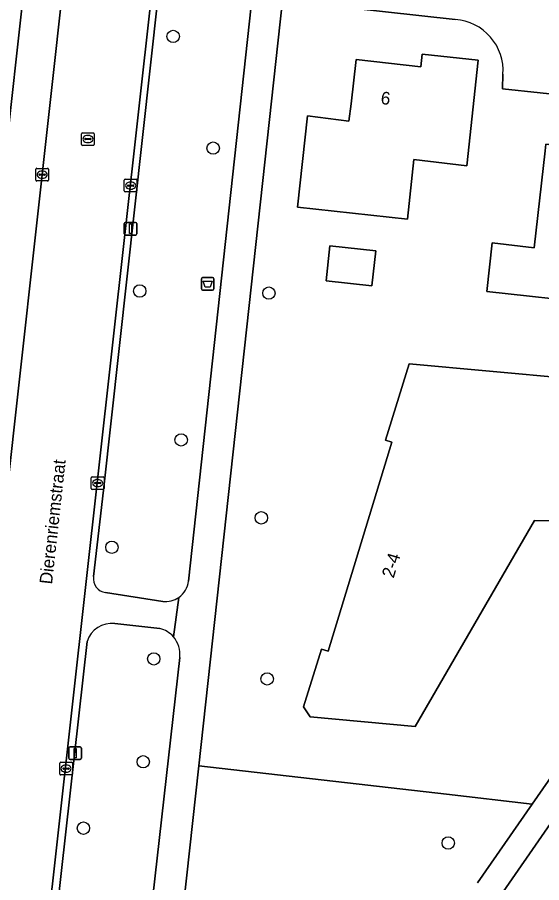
# Model space of a CAD drawing. Extents: x 161928 to 163071, y 386474 to 387428.
# Drawn here: x 162381 to 162422.4, y 386555.8 to 386624.1 of the extents above; entities that cross this region are included whole.
import ezdxf

# ---------------------------------------------------------------- set-up
doc = ezdxf.new("R2010")
doc.units = 0
for name, color, linetype in [('IMGEO_Afvalbak', 7, 'Continuous'), ('IMGEO_Boom', 7, 'Continuous'), ('IMGEO_Erf', 7, 'Continuous'), ('IMGEO_Groenvoorziening', 7, 'Continuous'), ('IMGEO_Kolk', 7, 'Continuous'), ('IMGEO_Lichtmast', 7, 'Continuous'), ('IMGEO_Openbare_ruimte_label', 7, 'Continuous'), ('IMGEO_Pand', 7, 'Continuous'), ('IMGEO_Pand_nummerreeks', 7, 'Continuous'), ('IMGEO_Rijbaan_lokaal_open', 7, 'Continuous'), ('IMGEO_Rioolput', 7, 'Continuous'), ('IMGEO_Voetpad_halfverhard', 7, 'Continuous'), ('IMGEO_Voetpad_open', 7, 'Continuous')]:
    doc.layers.add(name, color=color, linetype=linetype)

msp = doc.modelspace()

# ---------------------------------------------------------------- linework, layer by layer
at = {"layer": 'IMGEO_Afvalbak'}
for p, q in [((162395.637, 386603.544), (162396.427, 386603.544)), ((162396.427, 386603.544), (162395.637, 386603.544)), ((162395.537, 386602.644), (162395.537, 386603.444)), ((162395.537, 386603.444), (162395.537, 386602.644)), ((162396.527, 386603.444), (162396.527, 386602.644)), ((162396.527, 386602.644), (162396.527, 386603.444)), ((162396.427, 386602.544), (162395.637, 386602.544)), ((162395.637, 386602.544), (162396.427, 386602.544))]:
    msp.add_line(p, q, dxfattribs=at)
msp.add_lwpolyline([(162395.68, 386603.258), (162396.384, 386603.258), (162396.235, 386602.788), (162395.829, 386602.788), (162395.68, 386603.258)], dxfattribs=at)
for centre, start, end in [((162395.637, 386603.444), 90, 180), ((162395.637, 386603.444), 90, 180), ((162396.427, 386603.444), 0, 90), ((162396.427, 386603.444), 360, 90), ((162395.637, 386602.644), 180, 270), ((162395.637, 386602.644), 180, 270), ((162396.427, 386602.644), 270, 0), ((162396.427, 386602.644), 270, 0)]:
    msp.add_arc(centre, 0.1, start, end, dxfattribs=at)
at = {"layer": 'IMGEO_Boom'}
for centre in [(162393.313, 386622.577), (162396.47, 386613.757), (162390.674, 386602.473), (162400.87, 386602.31), (162393.945, 386590.715), (162400.269, 386584.564), (162388.477, 386582.239), (162391.784, 386573.428), (162400.731, 386571.846), (162390.949, 386565.307), (162386.227, 386560.062), (162415.023, 386558.889)]:
    msp.add_circle(centre, 0.489, dxfattribs=at)
at = {"layer": 'IMGEO_Erf'}
for points in [[(162339.209, 386621.347), (162355.58, 386619.565), (162355.871, 386622.182), (162359.601, 386621.768), (162363.559, 386621.328), (162363.268, 386618.711), (162367.629, 386618.152), (162367.92, 386620.769), (162371.65, 386620.355), (162375.608, 386619.915), (162375.317, 386617.298), (162380.485, 386616.728), (162382.904, 386638.649)], [(162415.579, 386623.904), (162401.954, 386625.399), (162400.548, 386612.657), (162395.336, 386564.99), (162414.895, 386562.738), (162421.638, 386561.962), (162444.564, 386594.917), (162445.356, 386594.4), (162447.893, 386598.102), (162459.435, 386614.943), (162461.829, 386626.715), (162463.03, 386628.501), (162454.731, 386634.129)], [(162420.711, 386632.302), (162420.785, 386633.326), (162432.793, 386632.1), (162431.191, 386617.163), (162419.313, 386618.428), (162419.342, 386619.587)]]:
    msp.add_lwpolyline(points, dxfattribs=at)
for points in [[(162416.478, 386612.365), (162412.312, 386612.86), (162411.796, 386608.156), (162403.125, 386609.105), (162403.907, 386616.296), (162407.183, 386615.892), (162407.356, 386617.249), (162407.76, 386620.758), (162412.848, 386620.178), (162412.963, 386621.184), (162417.396, 386620.697)], [(162427.798, 386613.519), (162427.904, 386614.49), (162432.344, 386614.004), (162432.984, 386613.934), (162433.301, 386616.837), (162438.553, 386614.056), (162438.131, 386610.243), (162433.019, 386610.774), (162431.843, 386609.181), (162432.687, 386609.076), (162432.443, 386606.776), (162431.59, 386606.862), (162431.44, 386605.691), (162427.261, 386606.138), (162426.729, 386601.484), (162418.06, 386602.436), (162418.497, 386606.268), (162421.797, 386605.894), (162422.663, 386613.546), (162422.722, 386614.071)], [(162408.995, 386602.89), (162405.381, 386603.285), (162405.682, 386606.038), (162409.296, 386605.643)], [(162425.465, 386590.661), (162426.325, 386592.104), (162427.514, 386591.415), (162423.4, 386584.325), (162421.823, 386584.367), (162412.423, 386568.098), (162404.117, 386568.856), (162403.593, 386569.649), (162405.008, 386574.185), (162405.538, 386574.032), (162410.561, 386590.527), (162410.059, 386590.685), (162411.937, 386596.728), (162424.617, 386595.56)]]:
    msp.add_lwpolyline(points, close=True, dxfattribs=at)
msp.add_arc((162415.314, 386619.874), 4.038, 355.91886, 86.23653, dxfattribs=at)
at = {"layer": 'IMGEO_Groenvoorziening'}
for points in [[(162399.459, 386624.985), (162398.864, 386625.051), (162392.123, 386625.803), (162387.805, 386586.742), (162387.016, 386579.921)], [(162394.525, 386579.576), (162399.459, 386624.985)], [(162440.702, 386585.864), (162418.182, 386553.338), (162417.153, 386552.158), (162415.924, 386550.971), (162414.594, 386549.899), (162413.174, 386548.95), (162411.674, 386548.131), (162410.108, 386547.45), (162408.487, 386546.912), (162406.824, 386546.52), (162405.699, 386546.306), (162403.155, 386545.99), (162400.592, 386545.903), (162398.032, 386546.045), (162393.322, 386546.486), (162403.05, 386533.82), (162404.756, 386535.016), (162406.178, 386535.73), (162416.358, 386539.36), (162419.33, 386541.041), (162421.413, 386542.569), (162422.397, 386543.77), (162427.166, 386551.666)], [(162387.976, 386578.658), (162392.493, 386577.97)], [(162392.272, 386575.826), (162388.696, 386576.225)], [(162386.515, 386574.809), (162383.807, 386550.605), (162391.149, 386549.775), (162393.833, 386573.529)], [(162421.638, 386561.962), (162414.895, 386562.738), (162395.336, 386564.99), (162393.659, 386549.647), (162400.359, 386548.883)], [(162417.322, 386555.758), (162421.638, 386561.962)]]:
    msp.add_lwpolyline(points, dxfattribs=at)
for centre, radius, start, end in [((162388.16, 386579.794), 1.151, 173.66933, 260.80724), ((162392.698, 386579.786), 1.839, 304.963, 353.4479), ((162392.716, 386579.782), 1.825, 262.98962, 304.58977), ((162388.489, 386574.157), 2.079, 84.27669, 161.71008), ((162391.743, 386573.781), 2.112, 41.29439, 75.49665), ((162391.75, 386573.792), 2.1, 352.796, 41.18918)]:
    msp.add_arc(centre, radius, start, end, dxfattribs=at)
at = {"layer": 'IMGEO_Kolk'}
for p, q in [((162382.472, 386611.233), (162382.472, 386612.085)), ((162382.547, 386612.159), (162383.399, 386612.159)), ((162382.96, 386611.939), (162382.985, 386611.939)), ((162383.473, 386612.085), (162383.473, 386611.233)), ((162383.399, 386611.159), (162382.547, 386611.159)), ((162382.731, 386611.653), (162382.731, 386611.665)), ((162383.169, 386611.616), (162382.771, 386611.616)), ((162382.774, 386611.702), (162383.172, 386611.702)), ((162382.983, 386611.379), (162382.958, 386611.379)), ((162383.215, 386611.665), (162383.215, 386611.653)), ((162389.454, 386610.371), (162389.454, 386611.223)), ((162389.529, 386611.297), (162390.381, 386611.297)), ((162389.942, 386611.077), (162389.967, 386611.077)), ((162390.455, 386611.223), (162390.455, 386610.371)), ((162389.713, 386610.791), (162389.713, 386610.803)), ((162390.151, 386610.754), (162389.753, 386610.754)), ((162389.756, 386610.84), (162390.154, 386610.84)), ((162389.965, 386610.517), (162389.94, 386610.517)), ((162390.197, 386610.803), (162390.197, 386610.791)), ((162390.381, 386610.297), (162389.529, 386610.297)), ((162386.928, 386587.808), (162387.78, 386587.808)), ((162386.853, 386586.882), (162386.853, 386587.734)), ((162387.112, 386587.302), (162387.112, 386587.314)), ((162387.55, 386587.265), (162387.152, 386587.265)), ((162387.155, 386587.351), (162387.553, 386587.351)), ((162387.341, 386587.588), (162387.366, 386587.588)), ((162387.596, 386587.314), (162387.596, 386587.302)), ((162387.854, 386587.734), (162387.854, 386586.882)), ((162387.78, 386586.808), (162386.928, 386586.808)), ((162387.364, 386587.028), (162387.339, 386587.028)), ((162384.434, 386565.265), (162385.286, 386565.265)), ((162384.359, 386564.339), (162384.359, 386565.191)), ((162384.618, 386564.759), (162384.618, 386564.771)), ((162385.056, 386564.722), (162384.658, 386564.722)), ((162384.661, 386564.808), (162385.059, 386564.808)), ((162384.847, 386565.045), (162384.872, 386565.045)), ((162385.102, 386564.771), (162385.102, 386564.759)), ((162385.36, 386565.191), (162385.36, 386564.339)), ((162385.286, 386564.265), (162384.434, 386564.265)), ((162384.87, 386564.485), (162384.845, 386564.485))]:
    msp.add_line(p, q, dxfattribs=at)
for points in [[(162382.472, 386611.233), (162382.472, 386612.085)], [(162382.547, 386612.159), (162383.399, 386612.159)], [(162383.473, 386612.085), (162383.473, 386611.233)], [(162383.399, 386611.159), (162382.547, 386611.159)], [(162389.454, 386610.371), (162389.454, 386611.223)], [(162389.529, 386611.297), (162390.381, 386611.297)], [(162390.455, 386611.223), (162390.455, 386610.371)], [(162390.381, 386610.297), (162389.529, 386610.297)], [(162386.928, 386587.808), (162387.78, 386587.808)], [(162386.853, 386586.882), (162386.853, 386587.734)], [(162387.854, 386587.734), (162387.854, 386586.882)], [(162387.78, 386586.808), (162386.928, 386586.808)], [(162384.434, 386565.265), (162385.286, 386565.265)], [(162384.359, 386564.339), (162384.359, 386565.191)], [(162385.36, 386565.191), (162385.36, 386564.339)], [(162385.286, 386564.265), (162384.434, 386564.265)]]:
    msp.add_lwpolyline(points, dxfattribs=at)
for centre, radius, start, end in [((162382.549, 386612.083), 0.0765, 91.55205, 178.44795), ((162382.549, 386612.083), 0.0765, 91.55205, 178.44795), ((162383.397, 386612.083), 0.0765, 1.55205, 88.44795), ((162383.397, 386612.083), 0.0765, 1.55205, 88.44795), ((162382.549, 386611.235), 0.0765, 181.55205, 268.44795), ((162382.549, 386611.235), 0.0765, 181.55205, 268.44795), ((162382.771, 386611.662), 0.0403, 85.87752, 175.75265), ((162382.768, 386611.652), 0.0366, 178.93798, 274.71019), ((162383.172, 386611.659), 0.043, 264.86636, 352.45326), ((162383.176, 386611.664), 0.0386, 1.73085, 96.63898), ((162383.397, 386611.235), 0.0765, 271.55205, 358.44795), ((162383.397, 386611.235), 0.0765, 271.55205, 358.44795), ((162389.531, 386611.221), 0.0765, 91.55205, 178.44795), ((162389.531, 386611.221), 0.0765, 91.55205, 178.44795), ((162390.379, 386611.221), 0.0765, 1.55205, 88.44795), ((162390.379, 386611.221), 0.0765, 1.55205, 88.44795), ((162389.531, 386610.373), 0.0765, 181.55205, 268.44795), ((162389.531, 386610.373), 0.0765, 181.55205, 268.44795), ((162389.753, 386610.8), 0.0403, 85.87752, 175.75265), ((162389.75, 386610.79), 0.0366, 178.93798, 274.71019), ((162390.154, 386610.797), 0.043, 264.86636, 352.45326), ((162390.158, 386610.802), 0.0386, 1.73085, 96.63898), ((162390.379, 386610.373), 0.0765, 271.55205, 358.44795), ((162390.379, 386610.373), 0.0765, 271.55205, 358.44795), ((162386.93, 386587.732), 0.0765, 91.55205, 178.44795), ((162386.93, 386587.732), 0.0765, 91.55205, 178.44795), ((162387.778, 386587.732), 0.0765, 1.55205, 88.44795), ((162387.778, 386587.732), 0.0765, 1.55205, 88.44795), ((162387.152, 386587.311), 0.0403, 85.87752, 175.75265), ((162387.149, 386587.301), 0.0366, 178.93798, 274.71019), ((162387.553, 386587.308), 0.043, 264.86636, 352.45326), ((162387.557, 386587.313), 0.0386, 1.73085, 96.63898), ((162386.93, 386586.884), 0.0765, 181.55205, 268.44795), ((162386.93, 386586.884), 0.0765, 181.55205, 268.44795), ((162387.778, 386586.884), 0.0765, 271.55205, 358.44795), ((162387.778, 386586.884), 0.0765, 271.55205, 358.44795), ((162384.436, 386565.189), 0.0765, 91.55205, 178.44795), ((162384.436, 386565.189), 0.0765, 91.55205, 178.44795), ((162385.284, 386565.189), 0.0765, 1.55205, 88.44795), ((162385.284, 386565.189), 0.0765, 1.55205, 88.44795), ((162384.658, 386564.768), 0.0403, 85.87752, 175.75265), ((162384.655, 386564.758), 0.0366, 178.93798, 274.71019), ((162385.059, 386564.765), 0.043, 264.86636, 352.45326), ((162385.063, 386564.77), 0.0386, 1.73085, 96.63898), ((162384.436, 386564.341), 0.0765, 181.55205, 268.44795), ((162384.436, 386564.341), 0.0765, 181.55205, 268.44795), ((162385.284, 386564.341), 0.0765, 271.55205, 358.44795), ((162385.284, 386564.341), 0.0765, 271.55205, 358.44795)]:
    msp.add_arc(centre, radius, start, end, dxfattribs=at)
for centre, major_axis, ratio, start_param, end_param in [((162382.959, 386611.659), (-0.387, 0.002), 0.722429, 4.712389, 7.853982), ((162382.984, 386611.659), (-0.39, 0.002), 0.717154, 1.570796, 4.712389), ((162389.941, 386610.797), (-0.387, 0.002), 0.722429, 4.712389, 7.853982), ((162389.966, 386610.797), (-0.39, 0.002), 0.717154, 1.570796, 4.712389), ((162387.34, 386587.308), (-0.387, 0.002), 0.722429, 4.712389, 7.853982), ((162387.365, 386587.308), (-0.39, 0.002), 0.717154, 1.570796, 4.712389), ((162384.846, 386564.765), (-0.387, 0.002), 0.722429, 4.712389, 7.853982), ((162384.871, 386564.765), (-0.39, 0.002), 0.717154, 1.570796, 4.712389)]:
    msp.add_ellipse(centre, major_axis=major_axis, ratio=ratio, start_param=start_param, end_param=end_param, dxfattribs=at)
at = {"layer": 'IMGEO_Lichtmast'}
for p, q in [((162389.451, 386606.994), (162389.451, 386607.794)), ((162389.451, 386607.794), (162389.451, 386606.994)), ((162389.551, 386607.894), (162390.341, 386607.894)), ((162390.341, 386607.894), (162389.551, 386607.894)), ((162390.441, 386607.794), (162390.441, 386606.994)), ((162390.441, 386606.994), (162390.441, 386607.794)), ((162390.341, 386606.894), (162389.551, 386606.894)), ((162389.551, 386606.894), (162390.341, 386606.894)), ((162385.077, 386565.583), (162385.077, 386566.383)), ((162385.077, 386566.383), (162385.077, 386565.583)), ((162385.177, 386566.483), (162385.967, 386566.483)), ((162385.967, 386566.483), (162385.177, 386566.483)), ((162386.067, 386566.383), (162386.067, 386565.583)), ((162386.067, 386565.583), (162386.067, 386566.383)), ((162385.967, 386565.483), (162385.177, 386565.483)), ((162385.177, 386565.483), (162385.967, 386565.483))]:
    msp.add_line(p, q, dxfattribs=at)
for points in [[(162389.871, 386607.769), (162390.021, 386607.769), (162390.021, 386607.019), (162389.871, 386607.019), (162389.871, 386607.769)], [(162385.497, 386566.358), (162385.647, 386566.358), (162385.647, 386565.608), (162385.497, 386565.608), (162385.497, 386566.358)]]:
    msp.add_lwpolyline(points, dxfattribs=at)
for centre, start, end in [((162389.551, 386607.794), 90, 180), ((162389.551, 386607.794), 90, 180), ((162390.341, 386607.794), 0, 90), ((162390.341, 386607.794), 360, 90), ((162389.551, 386606.994), 180, 270), ((162389.551, 386606.994), 180, 270), ((162390.341, 386606.994), 270, 0), ((162390.341, 386606.994), 270, 0), ((162385.177, 386566.383), 90, 180), ((162385.177, 386566.383), 90, 180), ((162385.967, 386566.383), 0, 90), ((162385.967, 386566.383), 360, 90), ((162385.177, 386565.583), 180, 270), ((162385.177, 386565.583), 180, 270), ((162385.967, 386565.583), 270, 0), ((162385.967, 386565.583), 270, 0)]:
    msp.add_arc(centre, 0.1, start, end, dxfattribs=at)
at = {"layer": 'IMGEO_Pand'}
for points in [[(162403.125, 386609.105), (162411.796, 386608.156), (162412.312, 386612.86), (162416.478, 386612.365), (162417.396, 386620.697), (162412.963, 386621.184), (162412.848, 386620.178), (162407.76, 386620.758), (162407.356, 386617.249), (162407.183, 386615.892), (162403.907, 386616.296)], [(162431.843, 386609.181), (162433.019, 386610.774), (162438.131, 386610.243), (162438.553, 386614.056), (162433.301, 386616.837), (162432.984, 386613.934), (162432.344, 386614.004), (162427.904, 386614.49), (162427.798, 386613.519), (162422.722, 386614.071), (162422.663, 386613.546), (162421.797, 386605.894), (162418.497, 386606.268), (162418.06, 386602.436), (162426.729, 386601.484), (162427.261, 386606.138), (162431.44, 386605.691), (162431.59, 386606.862), (162432.443, 386606.776), (162432.687, 386609.076)], [(162409.296, 386605.643), (162405.682, 386606.038), (162405.381, 386603.285), (162408.995, 386602.89)], [(162421.823, 386584.367), (162423.4, 386584.325), (162427.514, 386591.415), (162426.325, 386592.104), (162425.465, 386590.661), (162424.617, 386595.56), (162411.937, 386596.728), (162410.059, 386590.685), (162410.561, 386590.527), (162405.538, 386574.032), (162405.008, 386574.185), (162403.593, 386569.649), (162404.117, 386568.856), (162412.423, 386568.098)]]:
    msp.add_lwpolyline(points, close=True, dxfattribs=at)
at = {"layer": 'IMGEO_Rijbaan_lokaal_open'}
for points in [[(162391.61, 386625.86), (162392.296, 386632), (162392.862, 386637.456), (162385.93, 386638.274), (162377.724, 386564.413), (162376.367, 386550.047)], [(162419.342, 386619.587), (162419.313, 386618.428), (162431.191, 386617.163), (162432.793, 386632.1), (162420.785, 386633.326), (162420.711, 386632.302)], [(162416.503, 386628.855), (162402.493, 386630.278), (162401.954, 386625.399), (162415.579, 386623.904)], [(162375.565, 386506.213), (162378.144, 386505.94), (162379.433, 386517.155), (162381.15, 386532.061), (162391.61, 386625.86)]]:
    msp.add_lwpolyline(points, dxfattribs=at)
msp.add_arc((162415.314, 386619.874), 4.038, 355.91886, 86.23653, dxfattribs=at)
at = {"layer": 'IMGEO_Rioolput'}
for p, q in [((162386.085, 386614.044), (162386.085, 386614.896)), ((162386.16, 386614.97), (162387.012, 386614.97)), ((162386.344, 386614.464), (162386.344, 386614.476)), ((162386.387, 386614.513), (162386.785, 386614.513)), ((162386.573, 386614.75), (162386.598, 386614.75)), ((162386.828, 386614.476), (162386.828, 386614.464)), ((162387.086, 386614.896), (162387.086, 386614.044)), ((162387.012, 386613.97), (162386.16, 386613.97)), ((162386.782, 386614.427), (162386.384, 386614.427)), ((162386.596, 386614.19), (162386.571, 386614.19))]:
    msp.add_line(p, q, dxfattribs=at)
for points in [[(162386.085, 386614.044), (162386.085, 386614.896)], [(162386.16, 386614.97), (162387.012, 386614.97)], [(162387.086, 386614.896), (162387.086, 386614.044)], [(162387.012, 386613.97), (162386.16, 386613.97)]]:
    msp.add_lwpolyline(points, dxfattribs=at)
for centre, radius, start, end in [((162386.162, 386614.894), 0.0765, 91.55205, 178.44795), ((162386.162, 386614.894), 0.0765, 91.55205, 178.44795), ((162386.384, 386614.473), 0.0403, 85.87752, 175.75265), ((162386.381, 386614.463), 0.0366, 178.93798, 274.71019), ((162386.785, 386614.47), 0.043, 264.86636, 352.45326), ((162386.789, 386614.475), 0.0386, 1.73085, 96.63898), ((162387.01, 386614.894), 0.0765, 1.55205, 88.44795), ((162387.01, 386614.894), 0.0765, 1.55205, 88.44795), ((162386.162, 386614.046), 0.0765, 181.55205, 268.44795), ((162386.162, 386614.046), 0.0765, 181.55205, 268.44795), ((162387.01, 386614.046), 0.0765, 271.55205, 358.44795), ((162387.01, 386614.046), 0.0765, 271.55205, 358.44795)]:
    msp.add_arc(centre, radius, start, end, dxfattribs=at)
for centre, major_axis, ratio, start_param, end_param in [((162386.572, 386614.47), (-0.387, 0.002), 0.722429, 4.712389, 7.853982), ((162386.597, 386614.47), (-0.39, 0.002), 0.717154, 1.570796, 4.712389)]:
    msp.add_ellipse(centre, major_axis=major_axis, ratio=ratio, start_param=start_param, end_param=end_param, dxfattribs=at)
at = {"layer": 'IMGEO_Voetpad_halfverhard'}
for points in [[(162499.594, 386656.083), (162499.263, 386656.313), (162499.135, 386656.201), (162498.803, 386656.095), (162497.85, 386655.862), (162487.291, 386658.568), (162490.455, 386662.814), (162488.421, 386664.371), (162467.845, 386635.008), (162465.604, 386631.858), (162464.925, 386631.316), (162463.03, 386628.501), (162461.829, 386626.715), (162459.435, 386614.943), (162447.893, 386598.102), (162445.356, 386594.4), (162444.564, 386594.917), (162421.638, 386561.962), (162417.322, 386555.758)], [(162400.359, 386548.883), (162393.659, 386549.647), (162393.322, 386546.486), (162398.032, 386546.045), (162400.592, 386545.903), (162403.155, 386545.99), (162405.699, 386546.306), (162406.824, 386546.52), (162408.487, 386546.912), (162410.108, 386547.45), (162411.674, 386548.131), (162413.174, 386548.95), (162414.594, 386549.899), (162415.924, 386550.971), (162417.153, 386552.158), (162418.182, 386553.338), (162440.702, 386585.864), (162441.634, 386585.218), (162461.367, 386614.091), (162463.996, 386626.469)]]:
    msp.add_lwpolyline(points, dxfattribs=at)
at = {"layer": 'IMGEO_Voetpad_open'}
for points in [[(162400.548, 386612.657), (162401.954, 386625.399), (162402.493, 386630.278), (162403.939, 386643.891), (162404.515, 386649.308), (162401.514, 386649.68)], [(162402.028, 386648.883), (162400.099, 386631.151), (162399.536, 386631.212), (162398.864, 386625.051), (162399.459, 386624.985), (162394.525, 386579.576)], [(162382.904, 386638.649), (162380.485, 386616.728), (162380.29, 386614.963), (162375.635, 386572.782), (162375.483, 386571.401), (162374.673, 386564.034)], [(162377.724, 386564.413), (162385.93, 386638.274)], [(162387.016, 386579.921), (162387.805, 386586.742), (162392.123, 386625.803), (162391.61, 386625.86), (162381.15, 386532.061)], [(162393.659, 386549.647), (162395.336, 386564.99), (162400.548, 386612.657)], [(162392.493, 386577.97), (162387.976, 386578.658)], [(162393.752, 386578.279), (162393.33, 386575.175)], [(162393.33, 386575.175), (162393.752, 386578.279)], [(162388.696, 386576.225), (162392.272, 386575.826)], [(162381.749, 386532.21), (162383.556, 386548.365), (162390.976, 386547.518), (162391.149, 386549.775), (162383.807, 386550.605), (162386.515, 386574.809)], [(162393.833, 386573.529), (162391.149, 386549.775), (162390.976, 386547.518), (162389.007, 386529.591), (162388.138, 386529.688), (162387.869, 386527.229), (162386.677, 386516.292), (162385.46, 386505.167), (162384.878, 386500), (162384.399, 386495.945), (162383.844, 386490.932)]]:
    msp.add_lwpolyline(points, dxfattribs=at)
for centre, radius, start, end in [((162388.16, 386579.794), 1.151, 173.66933, 260.80724), ((162392.698, 386579.786), 1.839, 304.963, 353.4479), ((162392.716, 386579.782), 1.825, 262.98962, 304.58977), ((162388.489, 386574.157), 2.079, 84.27669, 161.71008), ((162391.743, 386573.781), 2.112, 41.29439, 75.49665), ((162391.75, 386573.792), 2.1, 352.796, 41.18918)]:
    msp.add_arc(centre, radius, start, end, dxfattribs=at)

# ---------------------------------------------------------------- texts
at = {"layer": 'IMGEO_Openbare_ruimte_label'}
msp.add_text('Dierenriemstraat', height=1, rotation=83.68512, dxfattribs=at).set_placement((162383.747, 386579.285))
at = {"layer": 'IMGEO_Pand_nummerreeks'}
for s, rotation, p in [('6', 353.49671, (162409.659, 386617.24)), ('2-4', 73.06364, (162410.709, 386579.753))]:
    msp.add_text(s, height=1, rotation=rotation, dxfattribs=at).set_placement(p)

doc.saveas('drawing.dxf')
